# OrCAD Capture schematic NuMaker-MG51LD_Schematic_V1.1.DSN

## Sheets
1 Nu-Link2-Me (TypeC-16): size A3; title: Nu-Link2-Me; rev: 1.0; company: CMHuang; note: Nu-Link2-Me
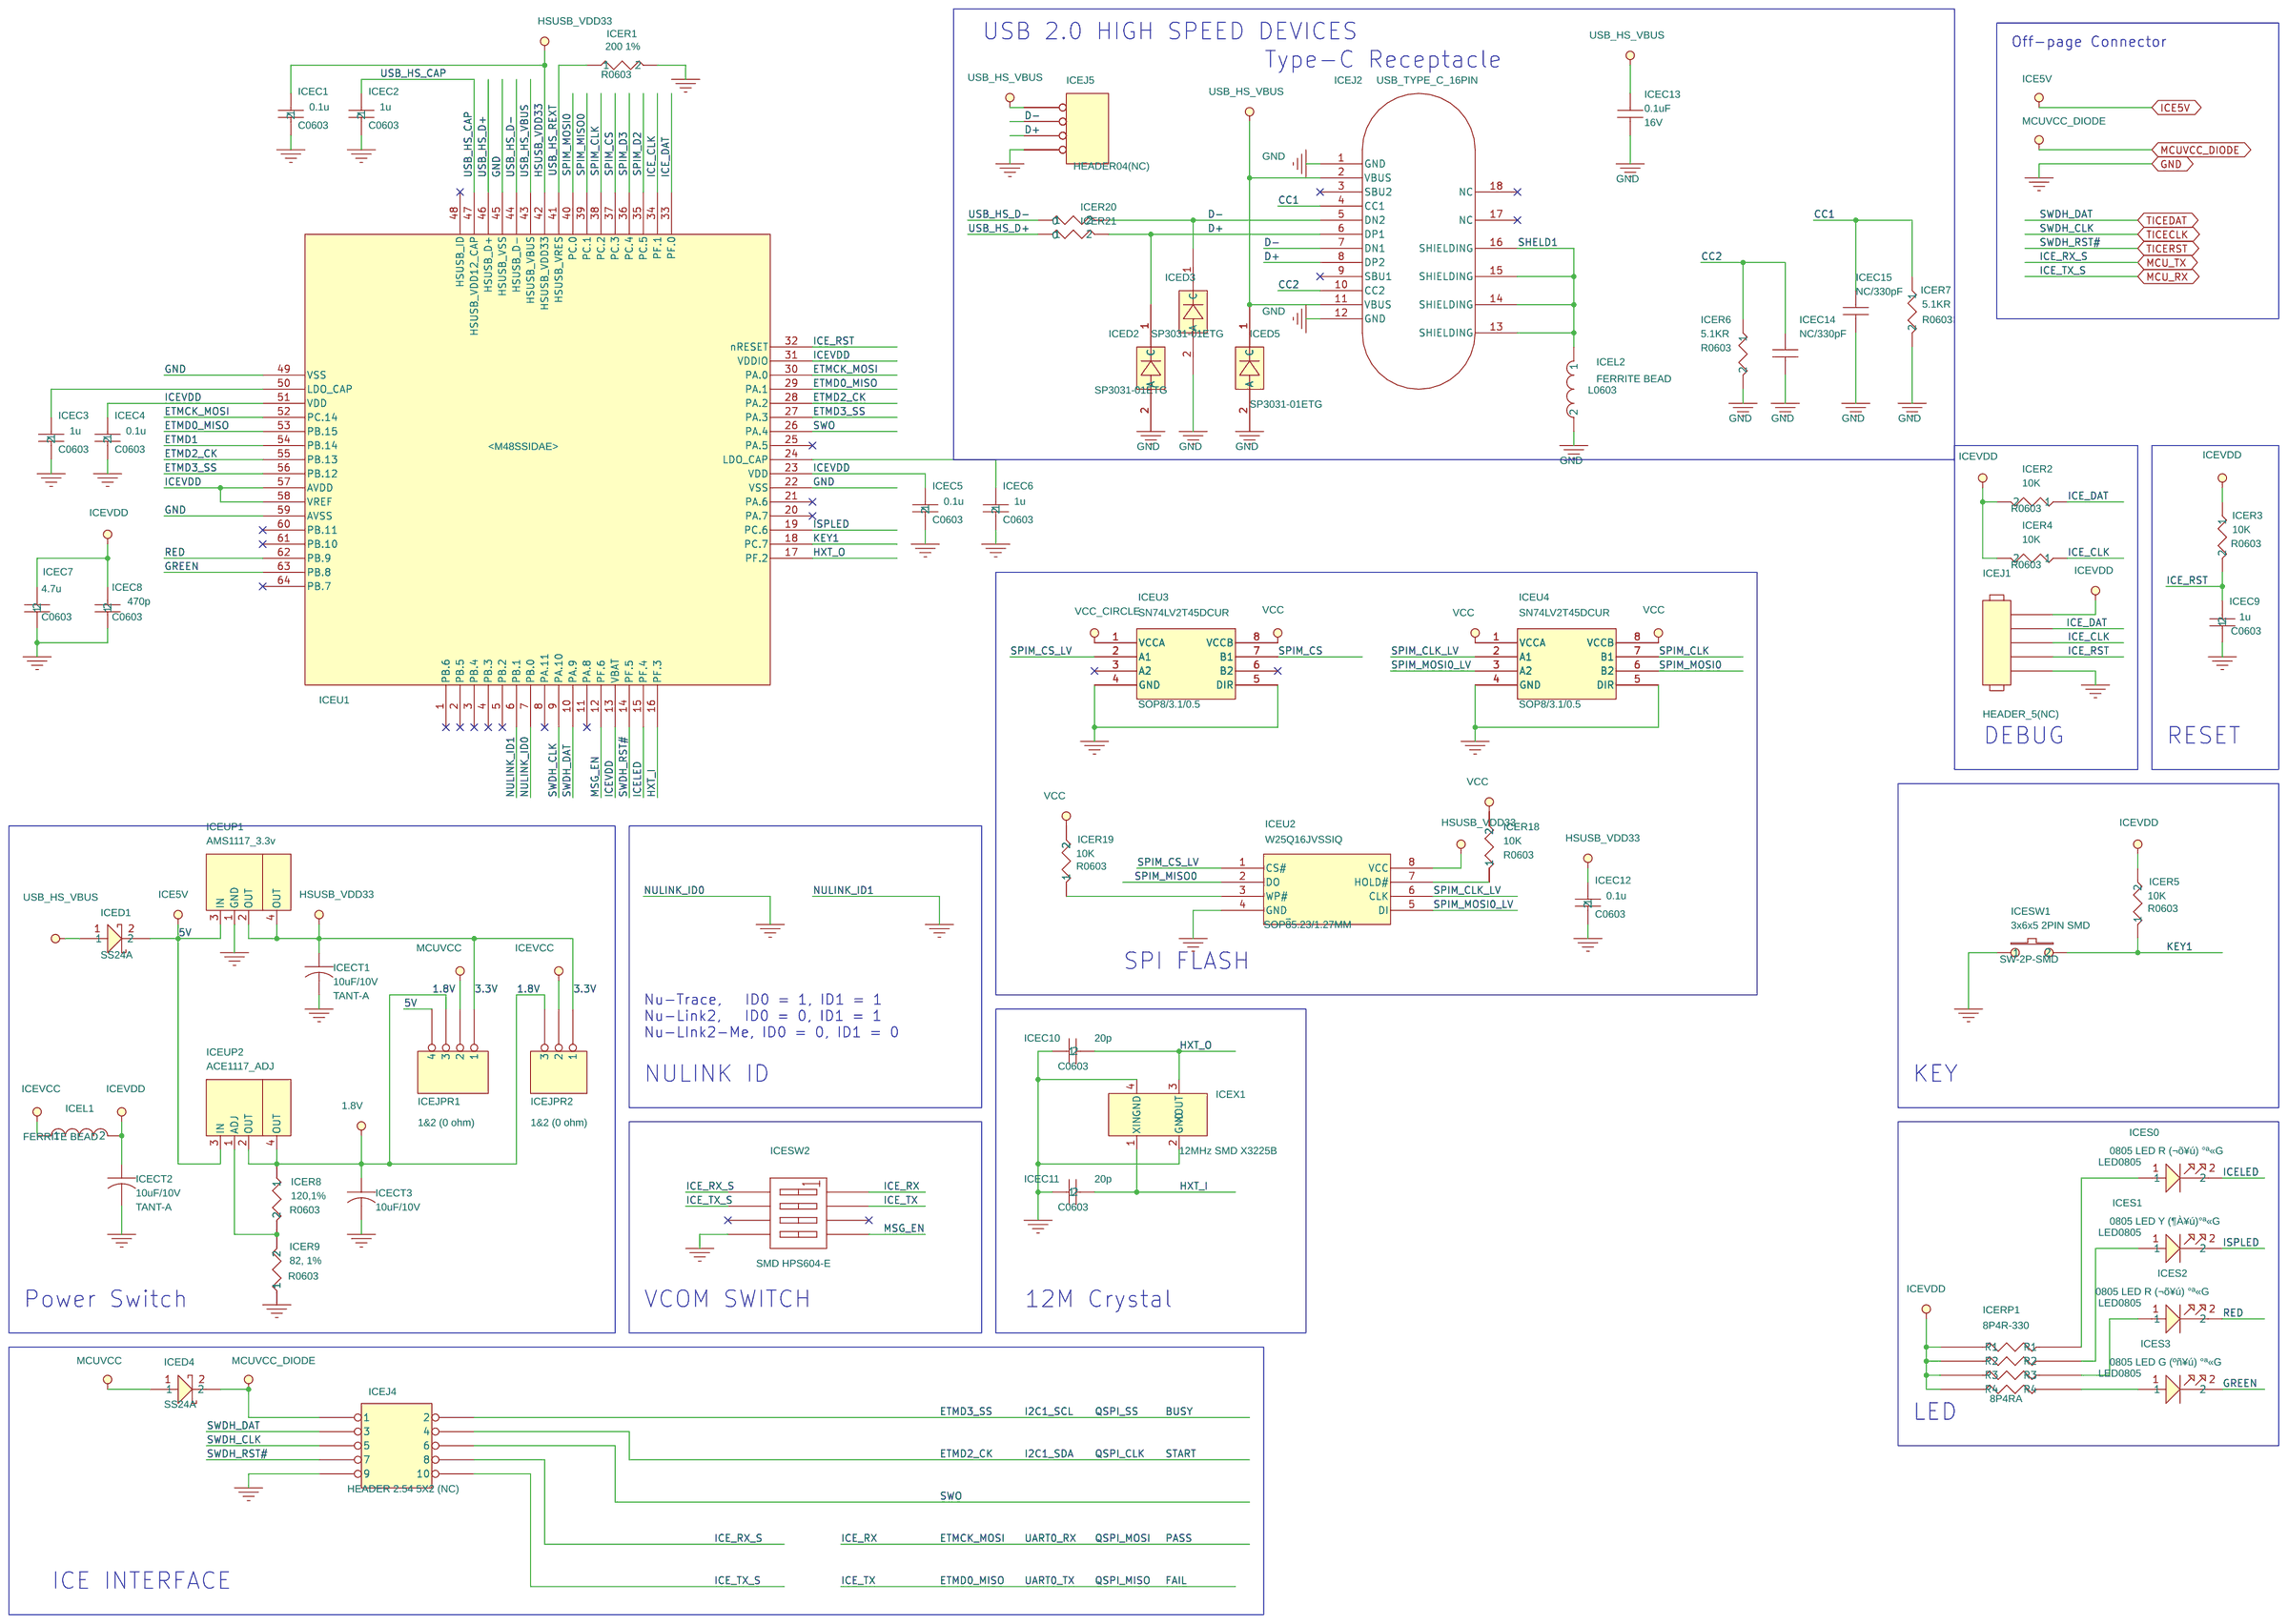
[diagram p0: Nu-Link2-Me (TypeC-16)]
2 MG51LD1AE: size Custom; title: MG51LD1AE; rev: v1.0; note: NuMaker-MG51LD
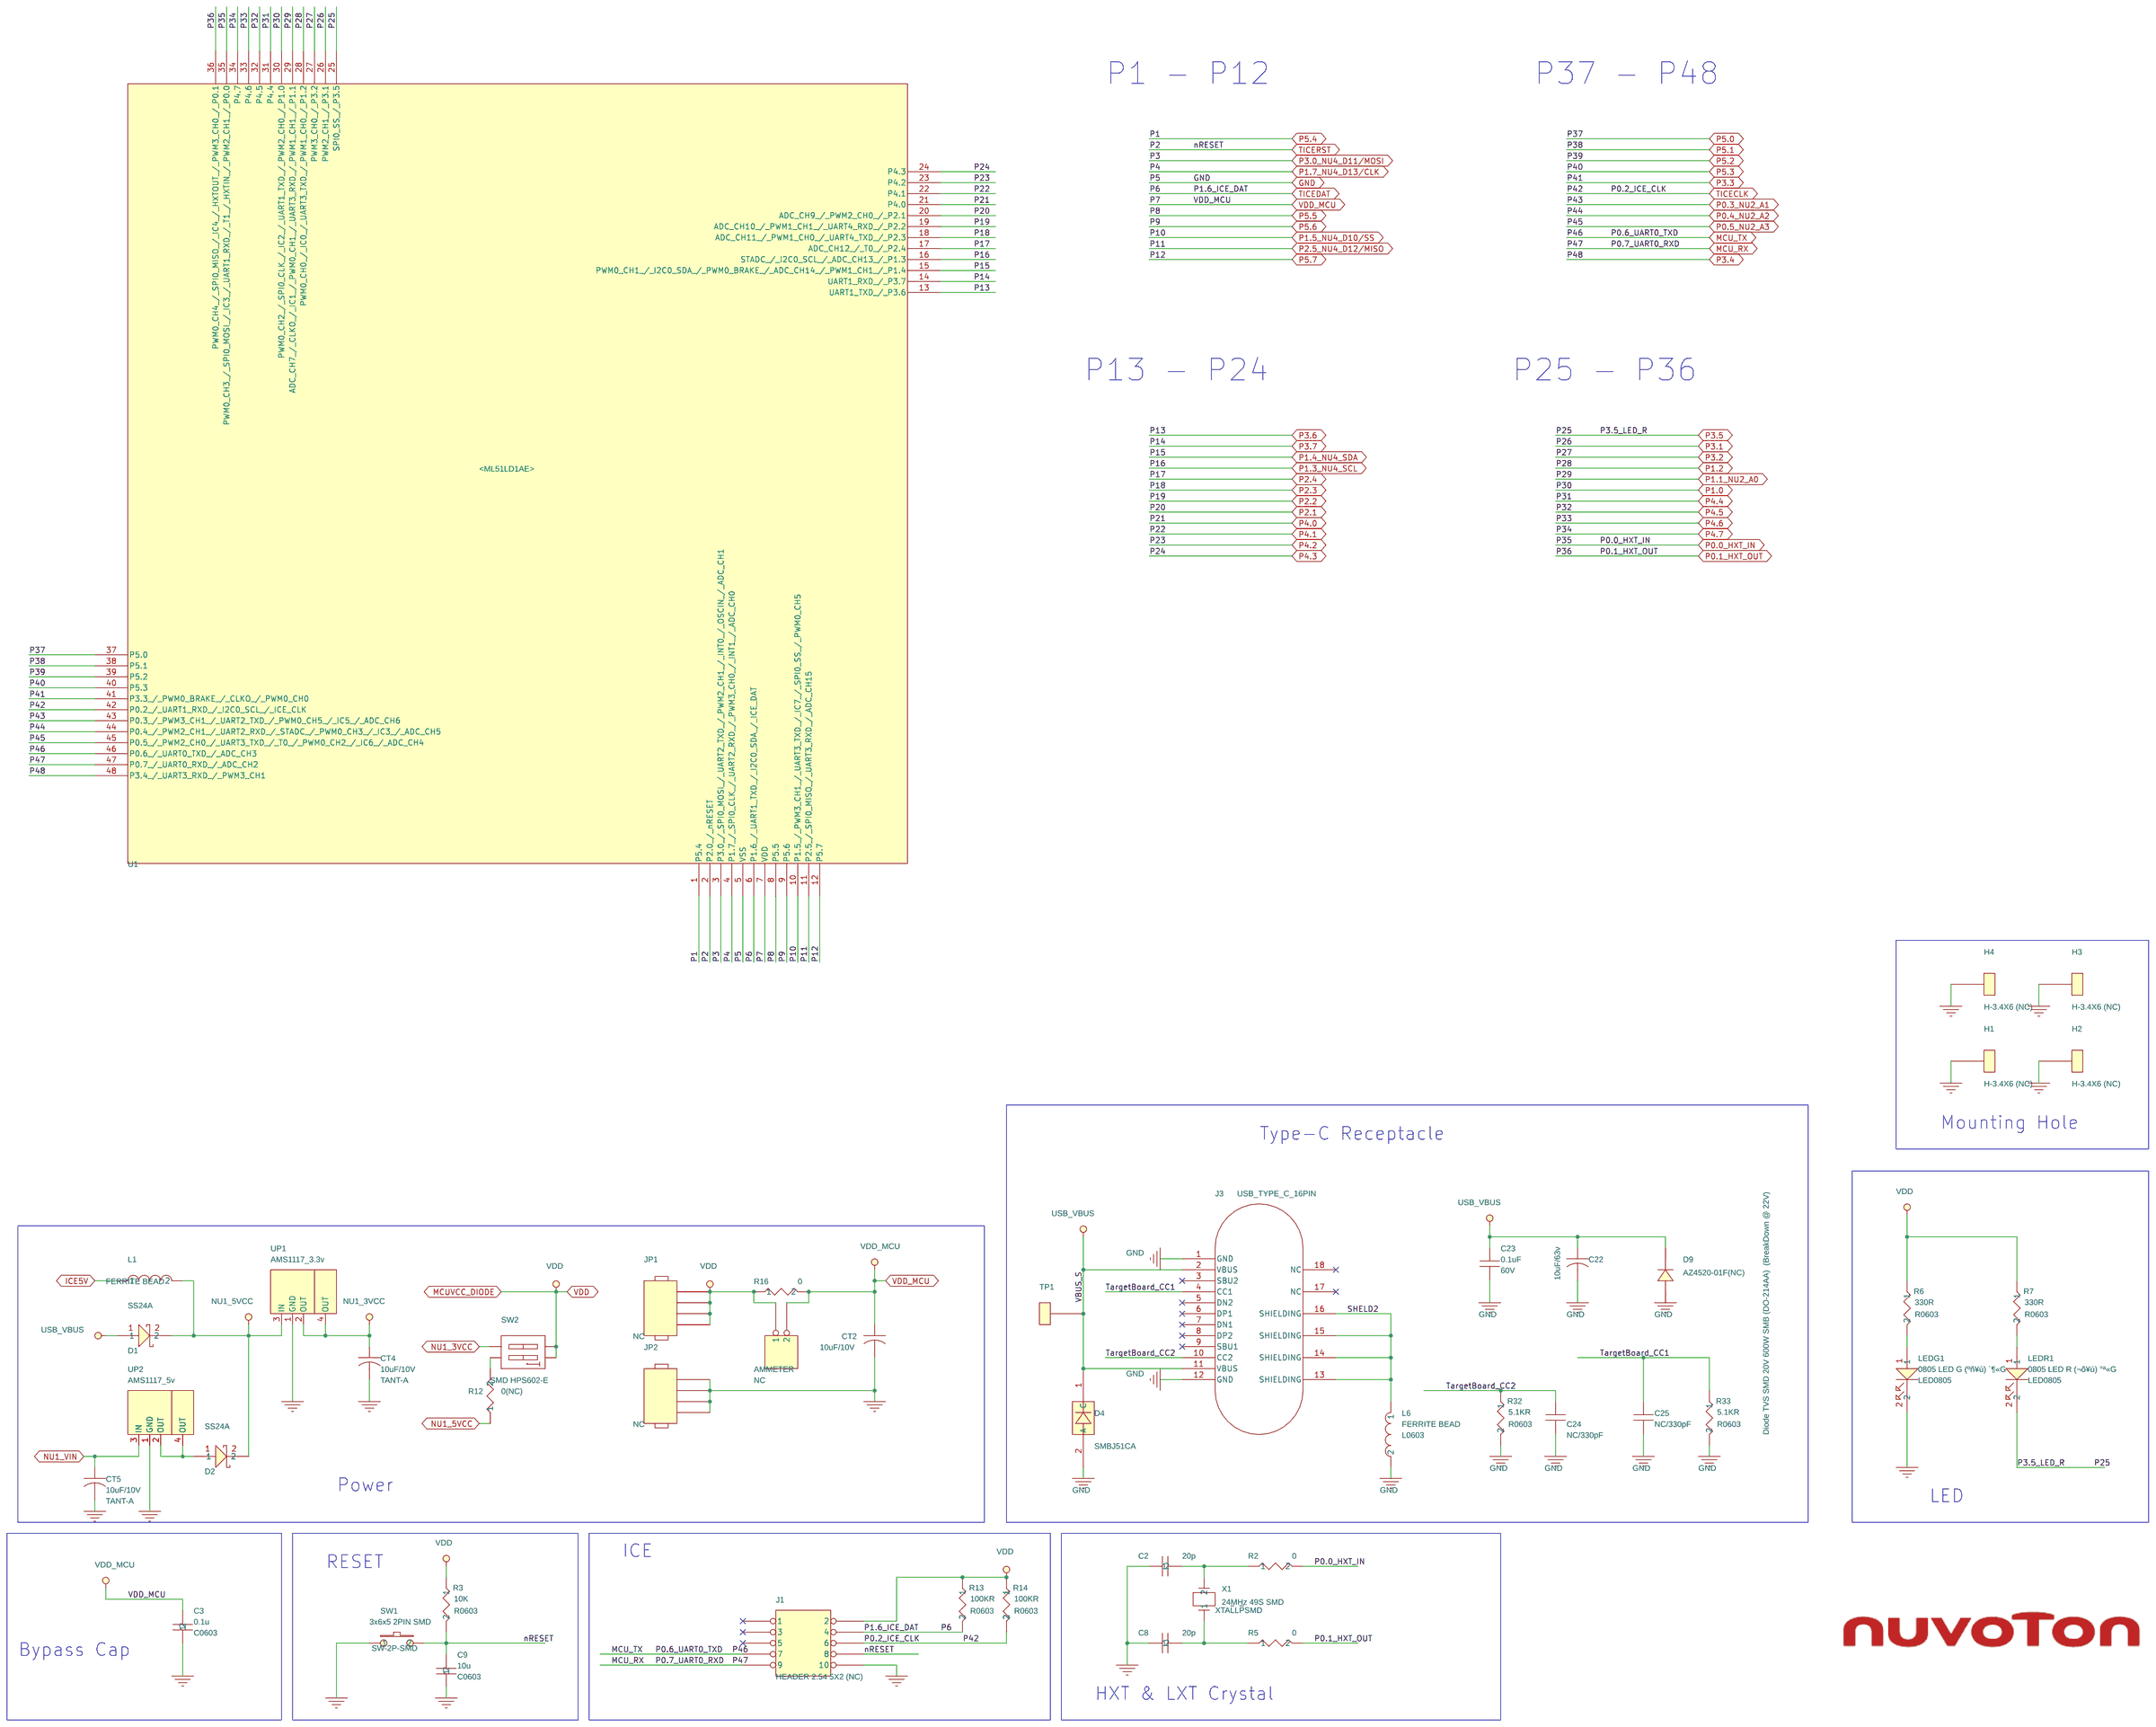
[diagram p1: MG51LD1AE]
3 Ext. Connector: size Custom; title: Ext. Connector; rev: v1.1; note: NuMaker-MG51LD
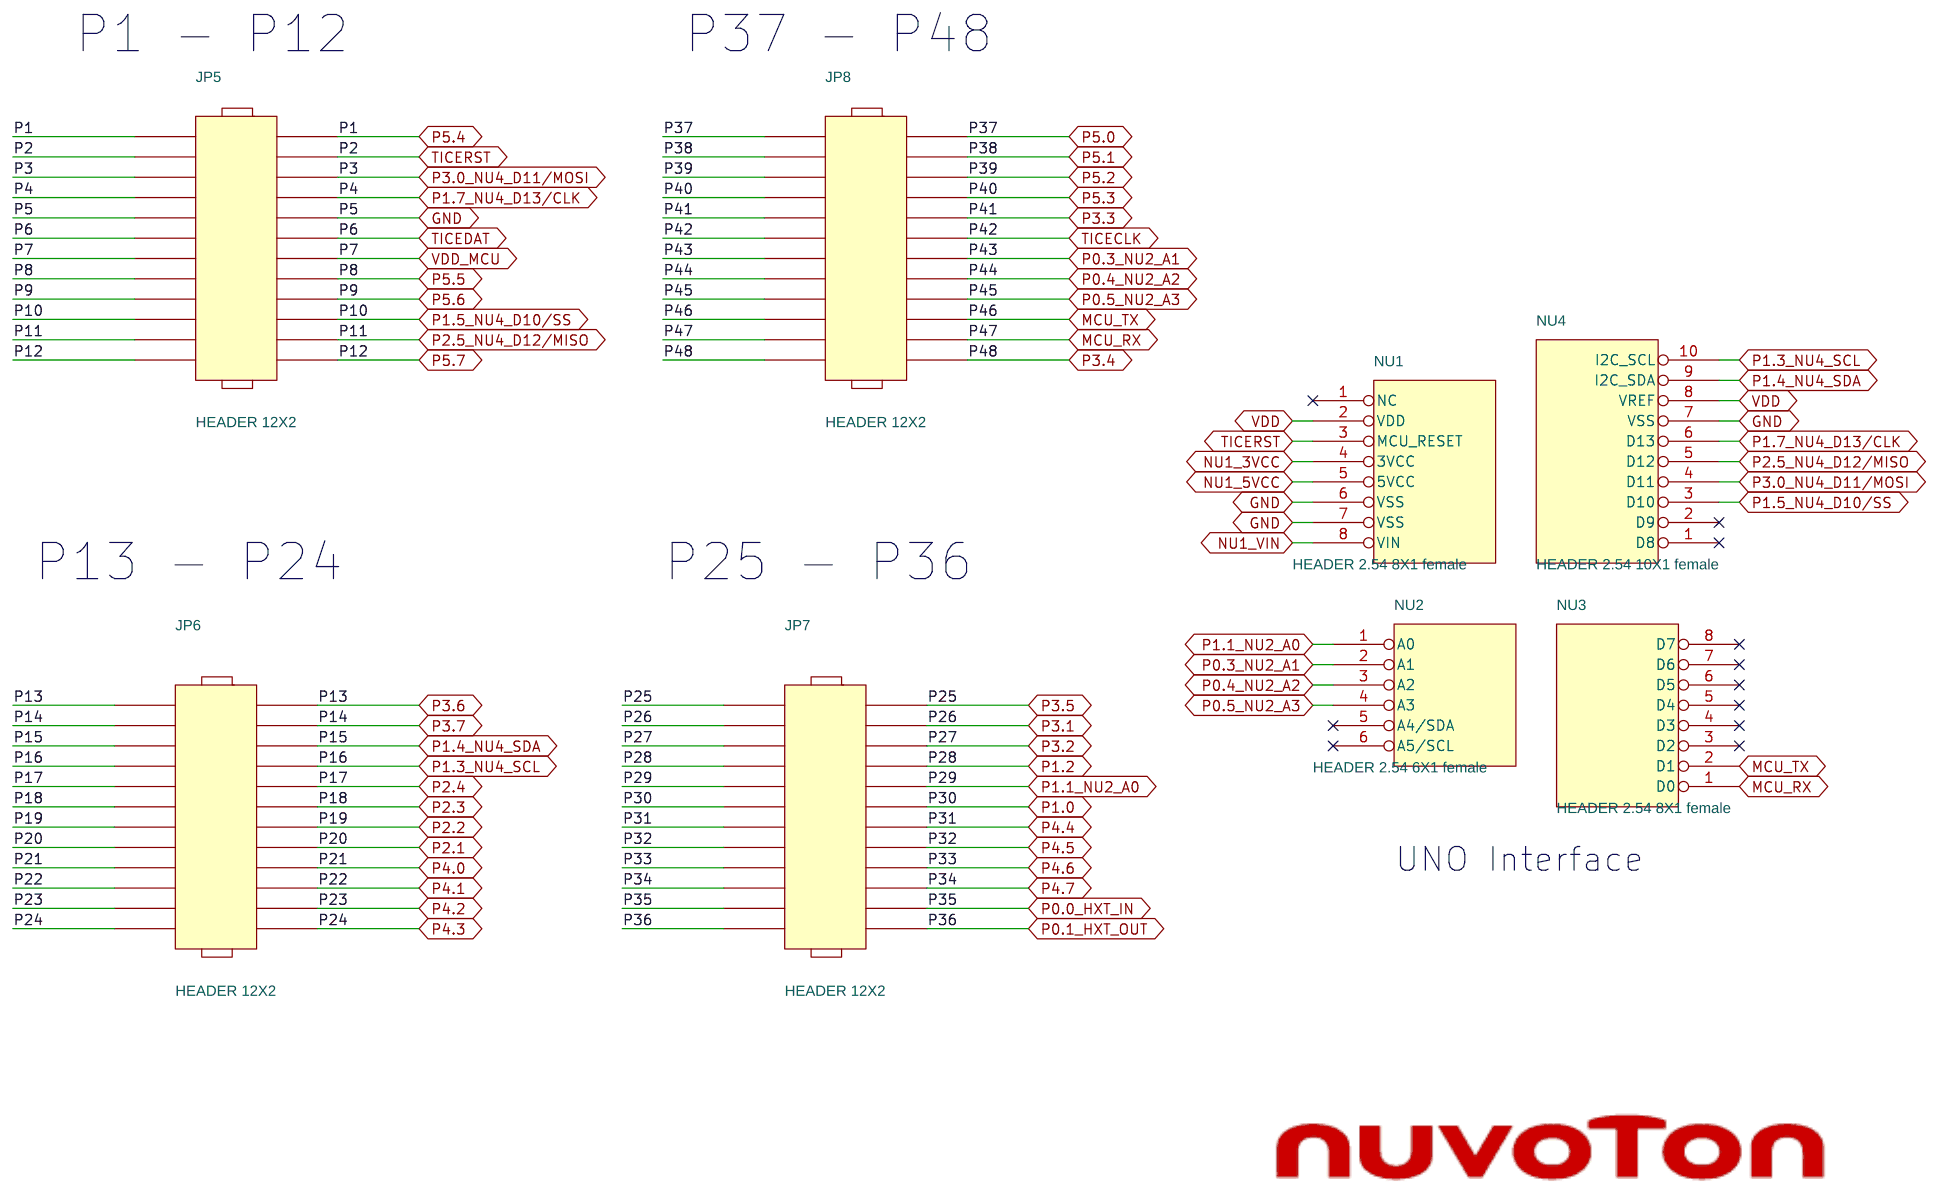
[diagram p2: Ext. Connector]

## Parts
sheet Ext. Connector
JP5  HEADER 12X2  [HEADER12X2/2.54]
JP6  HEADER 12X2  [HEADER12X2/2.54]
JP7  HEADER 12X2  [HEADER12X2/2.54]
JP8  HEADER 12X2  [HEADER12X2/2.54]
NU1  HEADER 2.54 8X1 female  [SIP-8P]
NU2  HEADER 2.54 6X1 female  [SIP-6P]
NU3  HEADER 2.54 8X1 female  [SIP-8P]
NU4  HEADER 2.54 10X1 female  [SIP-10P]
sheet MG51LD1AE
AMMETER  NC  [HEADER2X1]
C2  20p  [C0603]
C3  0.1u  [C0603]
C8  20p  [C0603]
C9  10u  [C0603]
C22  10uF/63v  [CES/6.3D/P]
C23  0.1uF  [C0603]
C24  NC/330pF  [C0603]
C25  NC/330pF  [C0603]
CT2  10uF/10V  [TANT-A]
CT4  10uF/10V  [TANT-A]
CT5  10uF/10V  [TANT-A]
D1  SS24A  [RB060L]
D2  SS24A  [RB060L]
D4  SMBJ51CA  [DO-214AA]
D9  AZ4520-01F(NC)  [DO-214AA/SMB]
H1  H-3.4X6 (NC)  [H-3.4X6]
H2  H-3.4X6 (NC)  [H-3.4X6]
H3  H-3.4X6 (NC)  [H-3.4X6]
H4  H-3.4X6 (NC)  [H-3.4X6]
J1  HEADER 2.54 5X2 (NC)  [HEADER5X2]
J3  USB_TYPE_C_16PIN  [FTPC16-FBR-XS-A21]
JP1  NC  [header1x4]
JP2  NC  [header1x4]
L1  FERRITE BEAD  [L0603]
L6  FERRITE BEAD  [L0603]
LEDG1  0805 LED G (ºñ¥ú) ´¶«G  [LED0805]
LEDR1  0805 LED R (¬õ¥ú) °ª«G  [LED0805]
R2  0  [R0603]
R3  10K  [R0603]
R5  0  [R0603]
R6  330R  [R0603]
R7  330R  [R0603]
R12  0(NC)  [R0603]
R13  100KR  [R0603]
R14  100KR  [R0603]
R16  0  [R0603]
R32  5.1KR  [R0603]
R33  5.1KR  [R0603]
SW1  3x6x5 2PIN SMD  [SW-2P-SMD]
SW2  SMD HPS602-E  [SW1X2]
TP1  TEST_POINT
U1  MG51LD1AE  [MCU_LQFP_48]
UP1  AMS1117_3.3v  [SOT-223-1]
UP2  AMS1117_5v  [SOT-223-1]
X1  24MHz 49S SMD  [XTAL\LP\SMD]
sheet Nu-Link2-Me (TypeC-16)
ICEC1  0.1u  [C0603]
ICEC2  1u  [C0603]
ICEC3  1u  [C0603]
ICEC4  0.1u  [C0603]
ICEC5  0.1u  [C0603]
ICEC6  1u  [C0603]
ICEC7  4.7u  [C0603]
ICEC8  470p  [C0603]
ICEC9  1u  [C0603]
ICEC10  20p  [C0603]
ICEC11  20p  [C0603]
ICEC12  0.1u  [C0603]
ICEC13  0.1uF  [C0603]
ICEC14  NC/330pF  [C0603]
ICEC15  NC/330pF  [C0603]
ICECT1  10uF/10V  [TANT-A]
ICECT2  10uF/10V  [TANT-A]
ICECT3  10uF/10V  [TANT-A]
ICED1  SS24A  [RB060L]
ICED2  SP3031-01ETG  [SOD882]
ICED3  SP3031-01ETG  [SOD882]
ICED4  SS24A  [RB060L]
ICED5  SP3031-01ETG  [SOD882]
ICEJ1  HEADER_5(NC)  [HEADER5X1]
ICEJ2  USB_TYPE_C_16PIN  [TID (00302-UCAF003-N)]
ICEJ4  HEADER 2.54 5X2 (NC)  [HEADER5X2]
ICEJ5  HEADER04(NC)  [HEADER04]
ICEJPR1  1&2 (0 ohm)  [R0603X3]
ICEJPR2  1&2 (0 ohm)  [R0603X2]
ICEL1  FERRITE BEAD  [L0603]
ICEL2  FERRITE BEAD  [L0603]
ICER1  200 1%  [R0603]
ICER2  10K  [R0603]
ICER3  10K  [R0603]
ICER4  10K  [R0603]
ICER5  10K  [R0603]
ICER6  5.1KR  [R0603]
ICER7  5.1KR  [R0603]
ICER8  120,1%  [R0603]
ICER9  82, 1%  [R0603]
ICER18  10K  [R0603]
ICER19  10K  [R0603]
ICER20  0  [R0603]
ICER21  0  [R0603]
ICERP1  8P4R-330  [8P4RA]
ICES0  0805 LED R (¬õ¥ú) °ª«G  [LED0805]
ICES1  0805 LED Y (¶À¥ú)°ª«G  [LED0805]
ICES2  0805 LED R (¬õ¥ú) °ª«G  [LED0805]
ICES3  0805 LED G (ºñ¥ú) °ª«G  [LED0805]
ICESW1  3x6x5 2PIN SMD  [SW-2P-SMD]
ICESW2  SMD HPS604-E  [SW1X4]
ICEU1  M48SSIDAE  [LQFP64_7x7_M48SSIDAE]
ICEU2  W25Q16JVSSIQ  [SOP8\5.23/1.27MM]
ICEU3  SN74LV2T45DCUR  [SOP8/3.1/0.5]
ICEU4  SN74LV2T45DCUR  [SOP8/3.1/0.5]
ICEUP1  AMS1117_3.3v  [SOT-223-1]
ICEUP2  ACE1117_ADJ  [SOT-223-1]
ICEX1  12MHz SMD X3225B  [CRYSTAL_SMD]

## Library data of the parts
JP5-JP8 = HEADER_12X2
NU1 = POWER_CONNECT_0
NU2 = ADC_CONNECT_0
NU3 = PWM0_CONNECT_0
NU4 = PWM1_CONNECT_1
AMMETER = HEADER_2
C2 = C_20p
C3 ICEC12 = CAP-C: Package: 0603; element_no: C0004
C8 = C_20p_1
C9 = CAP-C_1: Package: 0603; element_no: C0006
C22 CT2 CT4 CT5 ICECT1-ICECT3 = C_10uF_10V
C23 = CAPACITOR_NP: CAP CER X7R SMD 0.1uF 10% 50V 0603; Mount: M; Part Number: 880600286; Part Type: Capacitor\Ceramic; Raing/Power: 60V; Tolerance: 10%
C24 C25 ICEC14 ICEC15 = CAPACITOR_NP: CAP CER NPO SMD 330pF 5% 50V 0603; Mount: M; Part Number: 880600252; Part Type: Capacitor\Ceramic; Raing/Power: 50V; Tolerance: 5%
D1 ICED4 = D_SS24A_1
D2 ICED1 = D_SS24A
D4 = Schottky_Barrier_Diode_0: Diode SMD Schottky Barrier 30V; Mount: M; Part Number: 880900908
D9 = DIODE21: Diode TVS SMD 20V 600W SMB (DO-214AA)  (BreakDown @ 22V); Mount: M; Part Number: 880900866; Part Type: Diode
H1-H4 TP1 = TEST_POINT
ICEJ4 J1 = HEADER_5X2
J3 = USB_TYPE_C_9: CON USB 3.0 Type C receptical SMD & TH; Mount: M; Part Number: 880400981; Part Type: Connector
JP1 JP2 = HEADER_4
ICEL1 L1 = FERRITE_BEAD_1
ICEL2 L6 = FERRITE_BEAD
ICES0 LEDG1 = LED_0_1: Package: KP-2012; Vendor: Kingbright
ICES3 LEDR1 = LED_0: Package: KP-2012; Vendor: Kingbright
R2 = R_0_9
ICER19 R3 = R_0_10: Package: 0603
R5 = R_0_7
ICER6 R6 = R_0_3: Package: 0603
ICER18 R7 = R_0_6: Package: 0603
R12 = R_0_2
ICER9 R13 = R_0_8: Package: 0603
ICER2 R14 = R_0_5: Package: 0603
R16 = R_0_1
ICER4 R32 = R_0_4: Package: 0603
ICER8 R33 = R_0: Package: 0603
ICESW1 SW1 = SW_PUSHBUTTON_0
SW2 = SW_DIP-4_2
U1 = M032LD2AE_2: M032LD2AE: <ML51LD1AE>
ICEUP1 UP1 UP2 = TO-247_Regulator_10
X1 = Xtal_12MHz
ICEC1 = CAP-C_10: Package: 0603; element_no: C0004
ICEC2 = CAP-C_9: Package: 0603; element_no: C0006
ICEC3 = CAP-C_6: Package: 0603; element_no: C0006
ICEC4 = CAP-C_1: Package: 0603; element_no: C0004
ICEC5 = CAP-C_2: Package: 0603; element_no: C0004
ICEC6 = CAP-C_4: Package: 0603; element_no: C0006
ICEC7 = CAP-C_3: Package: 0603
ICEC8 = CAP-C_8: Package: 0603
ICEC9 = CAP-C_7: Package: 0603; element_no: C0006
ICEC10 = CAP-C_11: Package: 0603
ICEC11 = CAP-C_5: Package: 0603
ICEC13 = CAPACITOR_NP: CAP CER X7R SMD 0.1uF 10% 50V 0603; Mount: M; Part Number: 880600286; Part Type: Capacitor\Ceramic; Raing/Power: 16V; Tolerance: 10%
ICED2 ICED3 ICED5 = Schottky_Barrier_Diode_1: Diode SMD Schottky Barrier 30V; Mount: M; Part Number: 880900908
ICEJ1 = HEADER_5_v2
ICEJ2 = USB_TYPE_C_10: CON USB 3.0 Type C receptical SMD & TH; Mount: M; Part Number: 880400981; Part Type: Connector
ICEJ5 = HEADER_4_v2
ICEJPR1 = HEADER_3_0
ICEJPR2 = HEADER_3
ICER1 = R_0_7: Package: 0603
ICER3 = R_0_1: Package: 0603
ICER5 = R_0_2: Package: 0603
ICER7 = R_0_9: Package: 0603
ICER20 = R_33_1
ICER21 = R_33
ICERP1 = R-PACK8_0
ICES1 = LED_0_3: Package: KP-2012; Vendor: Kingbright
ICES2 = LED_0_2: Package: KP-2012; Vendor: Kingbright
ICESW2 = SW_DIP-4_SM
ICEU1 = M487SIDAE_0: M487SIDAE: <M48SSIDAE>
ICEU2 = W25P10_20_40_SOIC_0: Package: SOP8; Vendor: WINBOND
ICEU3 ICEU4 = SN74LV2T45
ICEUP2 = TO-247_Regulator_0
ICEX1 = Crystal_SMD_1

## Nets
1.8V: ICECT3.1 ICEJPR1.3 ICEJPR2.3 ICER8.1 ICEUP2.2(OUT) ICEUP2.4(OUT)
3.3V: ICEC1.1 ICEC12.1 ICECT1.1 ICEJPR1.1 ICEJPR2.1 ICER18.2 ICER19.2 ICEU1.42(HSUSB_VDD33) ICEU2.8(VCC) ICEU3.1(VCCA) ICEU4.1(VCCA) ICEUP1.2(OUT) ICEUP1.4(OUT)
GND: C2.1 C3.1 C8.1 C9.1 C22.2 C23.2 C24.2 C25.2 CT2.2 CT4.2 CT5.2 D4.2(A) D9.2(A) H1.1 H2.1 H3.1 H4.1 ICEC1.2 ICEC2.2 ICEC3.2 ICEC4.2 ICEC5.2 ICEC6.2 ICEC7.1 ICEC8.1 ICEC9.1 ICEC10.1 ICEC11.1 ICEC12.2 ICEC13.2 ICEC14.2 ICEC15.2 ICECT1.2 ICECT2.2 ICECT3.2 ICED2.2(A) ICED3.2(A) ICED5.2(A) ICEJ1.5 ICEJ2.1(GND) ICEJ2.12(GND) ICEJ4.9 ICEJ5.4 ICEL2.2 ICER1.2 ICER6.2 ICER7.2 ICER9.1 ICESW1.1 ICESW2.4(A4) ICEU1.6(PB.1) ICEU1.7(PB.0) ICEU1.22(VSS) ICEU1.45(HSUSB_VSS) ICEU1.49(VSS) ICEU1.59(AVSS) ICEU2.4(GND) ICEU3.4(GND) ICEU3.5(DIR) ICEU4.4(GND) ICEU4.5(DIR) ICEUP1.1(GND) ICEX1.2(GND) ICEX1.4(GND) J1.10 J3.1(GND) J3.12(GND) JP2.1 JP2.2 JP2.3 JP2.4 JP5.9 JP5.10 L6.2 LEDG1.2 NU1.6(VSS) NU1.7(VSS) NU4.7(VSS) R32.2 R33.2 SW1.1 U1.5(VSS) UP1.1(GND) UP2.1(GND)
VDD: AMMETER.1 ICED4.2 ICEJ4.1 J1.2 JP1.1 JP1.2 JP1.3 JP1.4 NU1.2(VDD) NU4.8(VREF) R3.1 R6.1 R7.1 R13.1 R14.1 R16.1 SW2.3(B1) SW2.4(B2)
VDD_MCU: AMMETER.2 C3.2 CT2.1 JP5.13 JP5.14 R16.2 U1.7(VDD)
BUSY: ICEJ4.2 ICEU1.27(PA.3) ICEU1.56(PB.12)
CC1: ICEC15.1 ICEJ2.4(CC1) ICER7.1
CC2: ICEC14.1 ICEJ2.10(CC2) ICER6.1
D+: ICED2.1(C) ICEJ2.6(DP1) ICEJ2.8(DP2) ICEJ5.3 ICER21.2
D-: ICED3.1(C) ICEJ2.5(DN2) ICEJ2.7(DN1) ICEJ5.2 ICER20.2
ETMD1: ICEU1.54(PB.14)
ETMD2_CK: ICEJ4.4 ICEU1.28(PA.2) ICEU1.55(PB.13)
GREEN: ICES3.2 ICEU1.63(PB.8)
HXT_I: ICEC11.2 ICEU1.16(PF.3) ICEX1.1(XIN)
HXT_O: ICEC10.2 ICEU1.17(PF.2) ICEX1.3(XOUT)
ICE5V: ICED1.2 ICEJPR1.4 ICEUP1.3(IN) ICEUP2.3(IN) L1.1
ICE_CLK: ICEJ1.3 ICER4.1 ICEU1.34(PF.1)
ICE_DAT: ICEJ1.2 ICER2.1 ICEU1.33(PF.0)
ICE_RST: ICEC9.2 ICEJ1.4 ICER3.2 ICEU1.32(nRESET)
ICE_RX: ICESW2.8(B1) ICEU1.30(PA.0) ICEU1.52(PC.14)
ICE_TX: ICESW2.7(B2) ICEU1.29(PA.1) ICEU1.53(PB.15)
ICELED: ICES0.2 ICEU1.15(PF.4)
ICEVCC: ICEJPR2.2 ICEL1.1
ICEVDD: ICEC4.1 ICEC5.1 ICEC7.2 ICEC8.2 ICECT2.1 ICEJ1.1 ICEL1.2 ICER2.2 ICER3.1 ICER4.2 ICER5.2 ICERP1.1(R1) ICERP1.3(R2) ICERP1.5(R3) ICERP1.7(R4) ICEU1.13(VBAT) ICEU1.23(VDD) ICEU1.31(VDDIO) ICEU1.51(VDD) ICEU1.57(AVDD) ICEU1.58(VREF) ICEU3.8(VCCB) ICEU4.8(VCCB)
ISPLED: ICES1.2 ICEU1.19(PC.6)
KEY1: ICER5.1 ICESW1.2 ICEU1.18(PC.7)
MCU_RX: ICEJ4.10 ICESW2.2(A2) J1.9 JP8.21 JP8.22 NU3.1(D0) U1.47(P0.7_/_UART0_RXD_/_ADC_CH2)
MCU_TX: ICEJ4.8 ICESW2.1(A1) J1.7 JP8.19 JP8.20 NU3.2(D1) U1.46(P0.6_/_UART0_TXD_/_ADC_CH3)
MCUVCC: ICED4.1 ICEJPR1.2
MSG_EN: ICESW2.5(B4) ICEU1.12(PF.6)
NU1_3VCC: CT4.1 NU1.4(3VCC) SW2.2(A2) UP1.2(OUT) UP1.4(OUT)
NU1_5VCC: D1.2 D2.2 L1.2 NU1.5(5VCC) R12.1 UP1.3(IN)
NU1_VIN: CT5.1 NU1.8(VIN) UP2.3(IN)
P0.0_HXT_IN: JP7.21 JP7.22 R2.2 U1.35(PWM0_CH3_/_SPI0_MOSI_/_IC3_/_UART1_RXD_/_T1_/_HXTIN_/_PWM2_CH1_/_P0.0)
P0.1_HXT_OUT: JP7.23 JP7.24 R5.2 U1.36(PWM0_CH4_/_SPI0_MISO_/_IC4_/_HXTOUT_/_PWM3_CH0_/_P0.1)
P0.3_NU2_A1: JP8.13 JP8.14 NU2.2(A1) U1.43(P0.3_/_PWM3_CH1_/_UART2_TXD_/_PWM0_CH5_/_IC5_/_ADC_CH6)
P0.4_NU2_A2: JP8.15 JP8.16 NU2.3(A2) U1.44(P0.4_/_PWM2_CH1_/_UART2_RXD_/_STADC_/_PWM0_CH3_/_IC3_/_ADC_CH5)
P0.5_NU2_A3: JP8.17 JP8.18 NU2.4(A3) U1.45(P0.5_/_PWM2_CH0_/_UART3_TXD_/_T0_/_PWM0_CH2_/_IC6_/_ADC_CH4)
P1.0: JP7.11 JP7.12 U1.30(PWM0_CH2_/_SPI0_CLK_/_IC2_/_UART1_TXD_/_PWM2_CH0_/_P1.0)
P1.1_NU2_A0: JP7.9 JP7.10 NU2.1(A0) U1.29(ADC_CH7_/_CLKO_/_IC1_/_PWM0_CH1_/_UART3_RXD_/_PWM1_CH1_/_P1.1)
P1.2: JP7.7 JP7.8 U1.28(PWM0_CH0_/_IC0_/_UART3_TXD_/_PWM1_CH0_/_P1.2)
P1.3_NU4_SCL: JP6.7 JP6.8 NU4.10(I2C_SCL) U1.16(STADC_/_I2C0_SCL_/_ADC_CH13_/_P1.3)
P1.4_NU4_SDA: JP6.5 JP6.6 NU4.9(I2C_SDA) U1.15(PWM0_CH1_/_I2C0_SDA_/_PWM0_BRAKE_/_ADC_CH14_/_PWM1_CH1_/_P1.4)
P1.5_NU4_D10/SS: JP5.19 JP5.20 NU4.3(D10) U1.10(P1.5_/_PWM3_CH1_/_UART3_TXD_/_IC7_/_SPI0_SS_/_PWM0_CH5)
P1.7_NU4_D13/CLK: JP5.7 JP5.8 NU4.6(D13) U1.4(P1.7_/_SPI0_CLK_/_UART2_RXD_/_PWM3_CH0_/_INT1_/_ADC_CH0)
P2.1: JP6.15 JP6.16 U1.20(ADC_CH9_/_PWM2_CH0_/_P2.1)
P2.2: JP6.13 JP6.14 U1.19(ADC_CH10_/_PWM1_CH1_/_UART4_RXD_/_P2.2)
P2.3: JP6.11 JP6.12 U1.18(ADC_CH11_/_PWM1_CH0_/_UART4_TXD_/_P2.3)
P2.4: JP6.9 JP6.10 U1.17(ADC_CH12_/_T0_/_P2.4)
P2.5_NU4_D12/MISO: JP5.21 JP5.22 NU4.5(D12) U1.11(P2.5_/_SPI0_MISO_/_UART3_RXD_/_ADC_CH15)
P3.0_NU4_D11/MOSI: JP5.5 JP5.6 NU4.4(D11) U1.3(P3.0_/_SPI0_MOSI_/_UART2_TXD_/_PWM2_CH1_/_INT0_/_OSCIN_/_ADC_CH1)
P3.1: JP7.3 JP7.4 U1.26(PWM2_CH1_/_P3.1)
P3.2: JP7.5 JP7.6 U1.27(PWM3_CH0_/_P3.2)
P3.3: JP8.9 JP8.10 U1.41(P3.3_/_PWM0_BRAKE_/_CLKO_/_PWM0_CH0)
P3.4: JP8.23 JP8.24 U1.48(P3.4_/_UART3_RXD_/_PWM3_CH1)
P3.5: JP7.1 JP7.2 LEDR1.2 U1.25(SPI0_SS_/_P3.5)
P3.6: JP6.1 JP6.2 U1.13(UART1_TXD_/_P3.6)
P3.7: JP6.3 JP6.4 U1.14(UART1_RXD_/_P3.7)
P4.0: JP6.17 JP6.18 U1.21(P4.0)
P4.1: JP6.19 JP6.20 U1.22(P4.1)
P4.2: JP6.21 JP6.22 U1.23(P4.2)
P4.3: JP6.23 JP6.24 U1.24(P4.3)
P4.4: JP7.13 JP7.14 U1.31(P4.4)
P4.5: JP7.15 JP7.16 U1.32(P4.5)
P4.6: JP7.17 JP7.18 U1.33(P4.6)
P4.7: JP7.19 JP7.20 U1.34(P4.7)
P5.0: JP8.1 JP8.2 U1.37(P5.0)
P5.1: JP8.3 JP8.4 U1.38(P5.1)
P5.2: JP8.5 JP8.6 U1.39(P5.2)
P5.3: JP8.7 JP8.8 U1.40(P5.3)
P5.4: JP5.1 JP5.2 U1.1(P5.4)
P5.5: JP5.15 JP5.16 U1.8(P5.5)
P5.6: JP5.17 JP5.18 U1.9(P5.6)
P5.7: JP5.23 JP5.24 U1.12(P5.7)
RED: ICES2.2 ICEU1.62(PB.9)
SHELD1: ICEJ2.13(SHIELDING) ICEJ2.14(SHIELDING) ICEJ2.15(SHIELDING) ICEJ2.16(SHIELDING) ICEL2.1
SHELD2: J3.13(SHIELDING) J3.14(SHIELDING) J3.15(SHIELDING) J3.16(SHIELDING) L6.1
SPIM_CLK: ICEU1.38(PC.2) ICEU4.7(B1)
SPIM_CLK_LV: ICEU2.6(CLK) ICEU4.2(A1)
SPIM_CS: ICEU1.37(PC.3) ICEU3.7(B1)
SPIM_CS_LV: ICEU2.1(CS#) ICEU3.2(A1)
SPIM_D2: ICEU1.35(PC.5)
SPIM_D3: ICEU1.36(PC.4)
SPIM_MISO0: ICEU1.39(PC.1) ICEU2.2(DO)
SPIM_MOSI0: ICEU1.40(PC.0) ICEU4.6(B2)
SPIM_MOSI0_LV: ICEU2.5(DI) ICEU4.3(A2)
SWO: ICEJ4.6 ICEU1.26(PA.4)
TargetBoard_CC1: C25.1 J3.4(CC1) R33.1
TargetBoard_CC2: C24.1 J3.10(CC2) R32.1
TICECLK: ICEJ4.5 ICEU1.9(PA.10) J1.6 JP8.11 JP8.12 R14.2 U1.42(P0.2_/_UART1_RXD_/_I2C0_SCL_/_ICE_CLK)
TICEDAT: ICEJ4.3 ICEU1.10(PA.9) J1.4 JP5.11 JP5.12 R13.2 U1.6(P1.6_/_UART1_TXD_/_I2C0_SDA_/_ICE_DAT)
TICERST: C9.2 ICEJ4.7 ICEU1.14(PF.5) J1.8 JP5.3 JP5.4 NU1.3(MCU_RESET) R3.2 SW1.2 U1.2(P2.0_/_nRESET)
USB_HS_CAP: ICEC2.1 ICEU1.47(HSUSB_VDD12_CAP)
USB_HS_D+: ICER21.1 ICEU1.46(HSUSB_D+)
USB_HS_D-: ICER20.1 ICEU1.44(HSUSB_D-)
USB_HS_REXT: ICER1.1 ICEU1.41(HSUSB_VRES)
USB_HS_VBUS: ICEC13.1 ICED1.1 ICED5.1(C) ICEJ2.2(VBUS) ICEJ2.11(VBUS) ICEJ5.1 ICEU1.43(HSUSB_VBUS)
USB_VBUS: C22.1 C23.1 D1.1 D4.1(C) D9.1(K) J3.2(VBUS) J3.11(VBUS) TP1.1
N16840819: ICEC6.1 ICEU1.24(LDO_CAP)
N16840960: ICEC3.1 ICEU1.50(LDO_CAP)
N17019924: ICER8.2 ICER9.2 ICEUP2.1(ADJ)
N17029977: ICERP1.8(R4) ICES3.1
N17029979: ICERP1.6(R3) ICES2.1
N17030004: ICERP1.4(R2) ICES1.1
N17030010: ICERP1.2(R1) ICES0.1
N17155328: ICER18.1 ICEU2.7(HOLD#)
N17155343: ICER19.1 ICEU2.3(WP#)
N17300228: LEDG1.1 R6.2
N17300229: LEDR1.1 R7.2
N17300273: R12.2 SW2.1(A1)
N17300285: D2.1 UP2.2(OUT) UP2.4(OUT)
N17313044: C8.2 R5.1 X1.1
N17313046: C2.2 R2.1 X1.2

Not connected (* = marked no-connect by the designer): ICEJ2 3(SBU2)* 9(SBU1)* 17(NC)* 18(NC)*; ICESW2 3(A3)* 6(B3)*; ICEU1 1(PB.6)* 2(PB.5)* 3(PB.4)* 4(PB.3)* 5(PB.2)* 8(PA.11)* 11(PA.8)* 20(PA.7)* 21(PA.6)* 25(PA.5)* 48(HSUSB_ID)* 60(PB.11)* 61(PB.10)* 64(PB.7)*; ICEU3 3(A2)* 6(B2)*; J1 1* 3* 5*; J3 3(SBU2)* 5(DN2)* 6(DP1)* 7(DN1)* 8(DP2)* 9(SBU1)* 17(NC)* 18(NC)*; NU1 1(NC)*; NU2 5(A4/SDA)* 6(A5/SCL)*; NU3 3(D2)* 4(D3)* 5(D4)* 6(D5)* 7(D6)* 8(D7)*; NU4 1(D8)* 2(D9)*

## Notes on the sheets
sheet 1
- USB 2.0 HIGH SPEED DEVICES
- Off-page Connector
- Type-C Receptacle
- DEBUG
- RESET
- SPI FLASH
- Nu-Trace,   ID0 = 1, ID1 = 1
  Nu-Link2,   ID0 = 0, ID1 = 1
  Nu-LInk2-Me, ID0 = 0, ID1 = 0
- NULINK ID
- KEY
- Power Switch
- VCOM SWITCH
- 12M Crystal
- LED
- ICE INTERFACE
sheet 2
- P1 - P12
- P37 - P48
- P13 - P24
- P25 - P36
- Type-C Receptacle
- Mounting Hole
- Power
- LED
- RESET
- ICE
- Bypass Cap
- HXT & LXT Crystal
sheet 3
- P1 - P12
- P37 - P48
- P13 - P24
- P25 - P36
- UNO Interface
